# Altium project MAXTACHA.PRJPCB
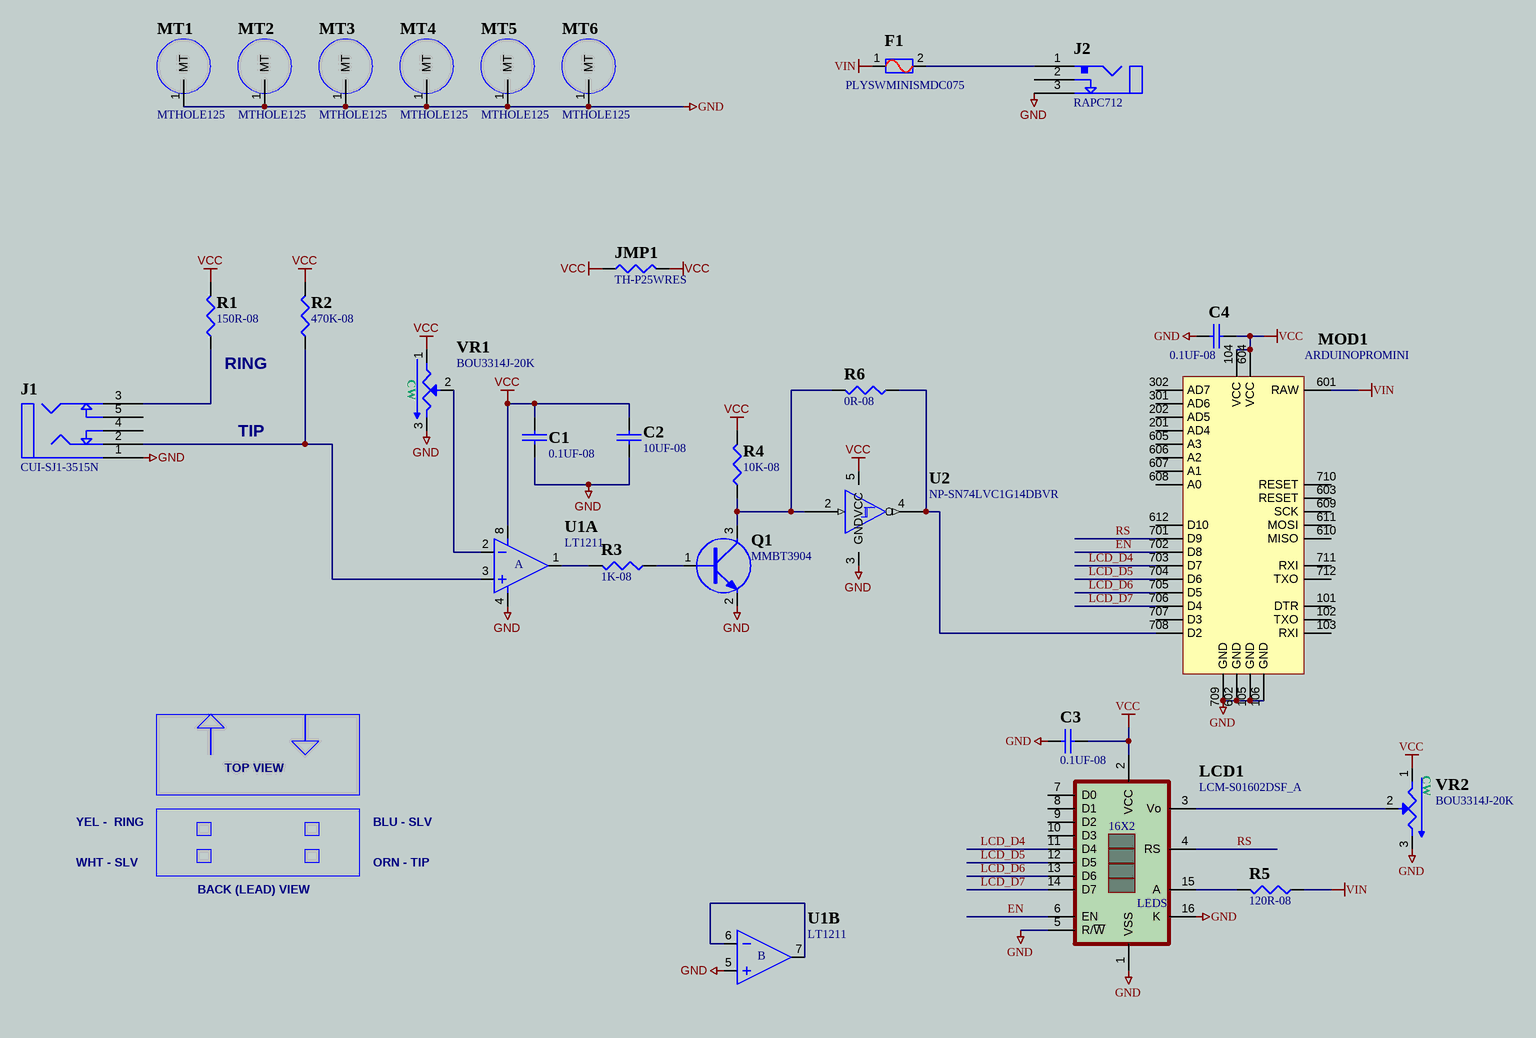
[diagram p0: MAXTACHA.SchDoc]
1 sheet, 27 parts. Net scope: global (net labels, ports and power ports of the same name join across sheets).
Board file: MAXTACHA.PcbDoc

## Sheet MAXTACHA.SchDoc: BSIZE.DOT
size B; Organization: WAM; Address1: 7839 Sabre Court Road; Address2: Manassas, VA 20109; Address3: Tele: 703-392-8575; Address4: Fax: 703-392-6911; DocumentNumber: 1; Revision: A; SheetNumber: 0; SheetTotal: 0

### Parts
C1  0.1UF-08  [_0805]
C2  10UF-08  [0805]
C3  0.1UF-08  [_0805]
C4  0.1UF-08  [_0805]
F1  PLYSWMINISMDC075  [POLYMSMDC]
J1  CUI-SJ1-3515N  [CUI-SJ1-3515N]
J2  RAPC712  [RAPC712]
JMP1  TH-P25WRES  [TH-RP25]
LCD1  LCM-S01602DSF_A  [LCM-S01602DSF_A]
MOD1  ARDUINOPROMINI  [ARDUINOPROMINI]
MT1  MTHOLE125  [MT125]
MT2  MTHOLE125  [MT125]
MT3  MTHOLE125  [MT125]
MT4  MTHOLE125  [MT125]
MT5  MTHOLE125  [MT125]
MT6  MTHOLE125  [MT125]
Q1  MMBT3904  [SOT-23]
R1  150R-08  [_0805]
R2  470K-08  [_0805]
R3  1K-08  [_0805]
R4  10K-08  [_0805]
R5  120R-08  [_0805]
R6  0R-08  [_0805]
U1  LT1211  [SO-8]  (parts A,B of 2)
U2  NP-SN74LVC1G14DBVR  [SOT23-5]
VR1  BOU3314J-20K  [BOU-3314J]
VR2  BOU3314J-20K  [BOU-3314J]

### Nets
GND: C1.2 C2.2 C3.2 C4.2 J1.1 J2.3 LCD1.1(VSS) LCD1.5(R/~{W}) LCD1.16(K) MOD1.105(GND) MOD1.106(GND) MOD1.602(GND) MOD1.709(GND) MT1.1(MT) MT2.1(MT) MT3.1(MT) MT4.1(MT) MT5.1(MT) MT6.1(MT) Q1.2(E) U1.4(V-) U1.5(INB+) U2.3(GND) VR1.3 VR2.3
VCC: C1.1 C2.1 C3.1 C4.1 JMP1.1 JMP1.2 LCD1.2(VCC) MOD1.104(VCC) MOD1.604(VCC) R1.2 R2.2 R4.2 U1.8(V+) U2.5(VCC) VR1.1 VR2.1
VIN: F1.1 MOD1.601(RAW) R5.1
EN: LCD1.6(EN) MOD1.702(D8)
LCD_D4: LCD1.11(D4) MOD1.703(D7)
LCD_D5: LCD1.12(D5) MOD1.704(D6)
LCD_D6: LCD1.13(D6) MOD1.705(D5)
LCD_D7: LCD1.14(D7) MOD1.706(D4)
RS: LCD1.4(RS) MOD1.701(D9)
NetF1_2: F1.2 J2.1
NetJ1_2: J1.2(TIP) R2.1 U1.3(INA+)
NetJ1_3: J1.3(RING) R1.1
NetLCD1_3: LCD1.3(Vo) VR2.2
NetLCD1_15: LCD1.15(A) R5.2
NetMOD1_708: MOD1.708(D2) R6.1 U2.4
NetQ1_1: Q1.1(B) R3.1
NetQ1_3: Q1.3(C) R4.1 R6.2 U2.2
NetR3_2: R3.2 U1.1(OUTA)
NetU1_2: U1.2(INA-) VR1.2
NetU1_6: U1.6(INB-) U1.7(OUTB)

Not connected (* = marked no-connect by the designer): J1 4(TIPSW) 5(RINGSW); J2 2; LCD1 7(D0) 8(D1) 9(D2) 10(D3); MOD1 101(DTR) 102(TXO) 103(RXI) 201(AD4) 202(AD5) 301(AD6) 302(AD7) 603(RESET) 605(A3) 606(A2) 607(A1) 608(A0) 609(SCK) 610(MISO) 611(MOSI) 612(D10) 707(D3) 710(RESET) 711(RXI) 712(TXO)

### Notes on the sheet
- (near R1) RING
- TIP
- TOP VIEW
- YEL -  RING
- BLU - SLV
- WHT - SLV
- BACK (LEAD) VIEW
- ORN - TIP

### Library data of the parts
C1 C3 C4 = 0CAP-08
C2 = .01UF-06
F1 = PLYSWMINISMDC075: POLYSWITCH 075
J1 = CUI-SJ1-3515N: CUI 3.5MM TRS STEREO AUDIO SAME AS RS 274-0246
J2 = RAPC712: SWCRFT DC PWR .1 PCB RGT ANG MATES WITH 760
JMP1 = TH-P25WRES: RESISTOR 1/4W
LCD1 = LCM-S01602DSF_A: LUMEX 16X2 LCD MODULE LED BKLITE
R1-R6 = 0805R
U2 = SN74LVC1G14DBVR: TI SCHMITT TRIG INV  296-11607-1-ND
VR1 VR2 = BOU3314J: BOURNS 3314J 4MM TRIMMER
